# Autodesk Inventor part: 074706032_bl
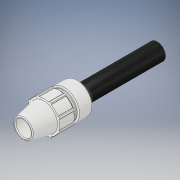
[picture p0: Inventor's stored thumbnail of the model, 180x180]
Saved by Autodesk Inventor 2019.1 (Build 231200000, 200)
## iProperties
Created: 2022-07
Part Number: 074706032_bl
Material: PVC-Piping
Description: Plasson Adjustable Elbow 32 x 32 mm
Document SubType Name: Modeling
Designer: comp2
Density: 1.4 g/cm^3
Appearance: Smooth - White
Author: comp2
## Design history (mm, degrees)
derived "07470.ipt"
feature "Solid1::07470.ipt" dims "ScaleForDerivedMember" = 10
feature "Solid2::07470.ipt" dims "ScaleForDerivedMember" = 10
feature "Solid3::07470.ipt" dims "ScaleForDerivedMember" = 10
feature "Solid4::07470.ipt" dims "ScaleForDerivedMember" = 10
tag "TaggingFeature1"
body "Solid1"
body "Solid2"
body "Solid3"
body "Solid4"
other parameters: "d0" = 257 [user parameter], "d2" = 32 [user parameter], "d6" = 64 [user parameter], "d7" = 26.24 [user parameter], "d8" = 32 [user parameter], "d9" = 45 deg [user parameter], "d10" = 16 [user parameter], "d12" = 35.2 [user parameter], "d13" = 175 [user parameter], "d15" = 1 [user parameter], "d16" = 25.2 [user parameter], "d17" = 46.4 [user parameter], "d19" = 52.8 [user parameter], "d20" = 8 deg [user parameter], "d21" = 24.85 [user parameter], "d22" = 3.2 [user parameter], "d24" = 6 [user parameter], "d25" = 1.285 [user parameter], "d26" = 1.285 [user parameter], "d27" = 85 deg [user parameter], "d28" = 71 [user parameter], "d30" = 28.4 [user parameter], "d31" = 2 [user parameter], "d32" = 27.2 [user parameter], "d33" = 2.84 [user parameter], "d38" = 59.52 [user parameter], "d39" = 35 deg [user parameter], "d40" = 17.5 deg [user parameter], "d42" = 0 [user parameter], "d43" = 1.28 [user parameter], "d47" = 360 deg [user parameter], "d49" = 1.6 [user parameter], "d50" = 6.39 [user parameter], "l_" = 71 [user parameter], "H_" = 257 [user parameter], "E_" = 64 [user parameter], "d" = 32 [user parameter], "d1" = 32 [user parameter], "d23" = 6 [user parameter]
